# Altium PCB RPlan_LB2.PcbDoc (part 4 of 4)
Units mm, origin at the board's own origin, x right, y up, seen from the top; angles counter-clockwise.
Board outline 38.2 x 43.28 mm, 2 copper layers (Top Layer, Bottom Layer); 36 components, 100 nets, 269 pads, 31 vias.
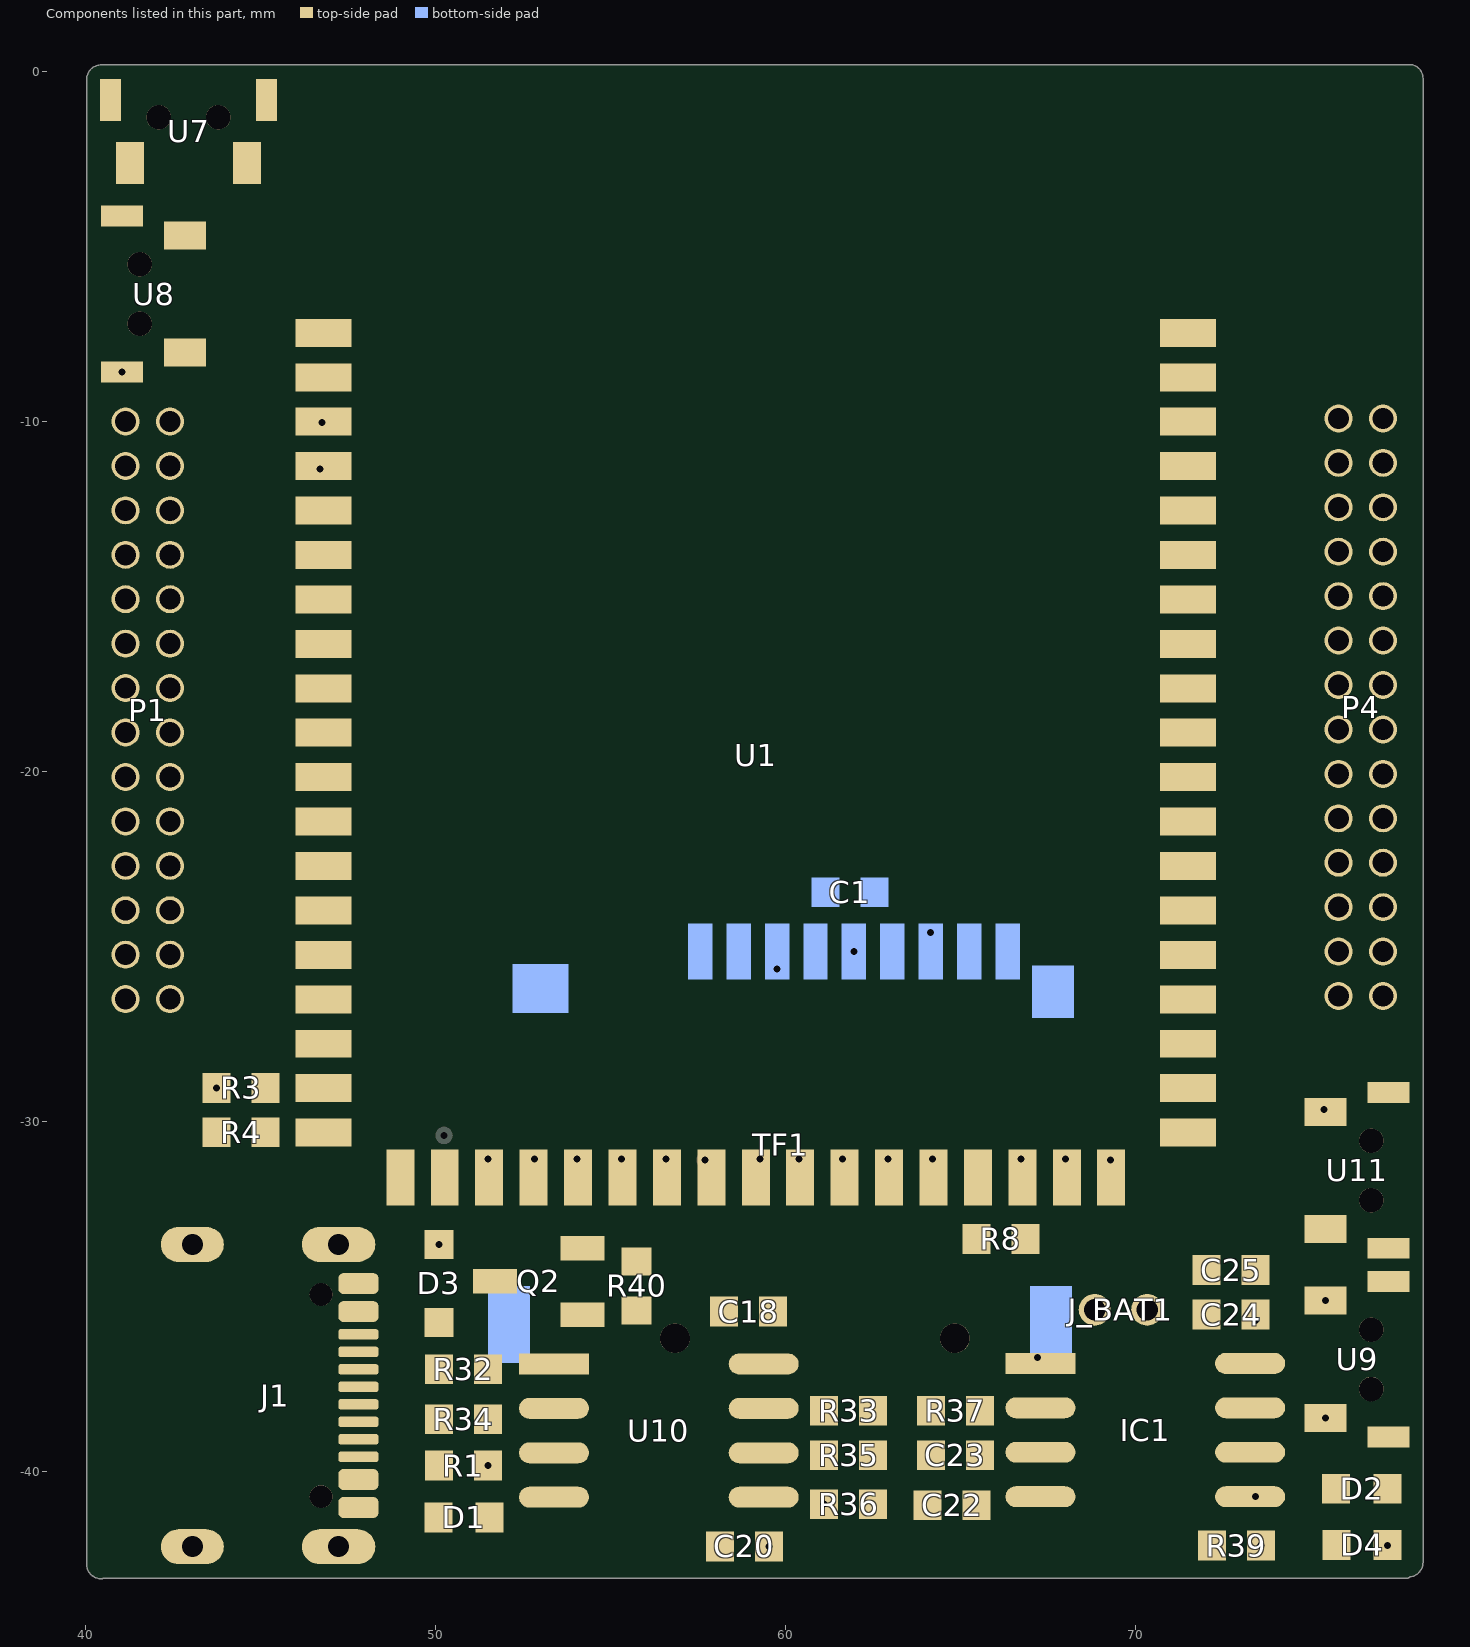
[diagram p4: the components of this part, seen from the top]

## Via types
v1: diameter 0.5, hole 0.3, Top Layer to Bottom Layer, 28 vias
v2: diameter 0.4, hole 0.2, Top Layer to Bottom Layer, 3 vias

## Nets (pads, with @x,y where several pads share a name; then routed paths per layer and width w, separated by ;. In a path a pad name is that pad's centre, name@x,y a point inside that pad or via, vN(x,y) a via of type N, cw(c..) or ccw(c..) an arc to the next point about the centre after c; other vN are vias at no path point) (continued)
copper on no net: (continued)
  Bottom Layer w0.025: 60.612,-15.207 60.84,-15.207 ; 60.612,-15.182 60.84,-15.182 ; 60.612,-15.156 60.84,-15.156 ; 60.612,-15.131 60.84,-15.131 ; 60.612,-15.105 61.196,-15.105 ; 60.815,-21.049 61.196,-21.049 ; 60.815,-21.024 61.145,-21.024 ; 60.815,-20.998 61.145,-20.998 ; 60.815,-20.973 61.145,-20.973 ; 60.815,-20.947 61.145,-20.947 ; 60.815,-20.922 61.145,-20.922 ; 60.815,-20.897 61.145,-20.897 ; 60.815,-20.871 61.145,-20.871 ; 60.815,-20.846 61.145,-20.846 ; 60.815,-20.82 61.196,-20.82 ; 60.815,-20.795 61.196,-20.795 ; 60.815,-20.77 61.196,-20.77 ; 60.815,-19.068 61.196,-19.068 ; 60.815,-19.042 61.145,-19.042 ; 60.815,-19.017 61.145,-19.017 ; 60.815,-18.992 61.145,-18.992 ; 60.815,-18.966 61.196,-18.966 ; 60.815,-18.941 61.196,-18.941 ; 60.815,-18.915 61.196,-18.915 ; 60.815,-18.89 61.196,-18.89 ; 60.815,-18.865 61.196,-18.865 ; 60.815,-18.839 61.196,-18.839 ; 60.815,-18.814 61.196,-18.814 ; 60.815,-18.788 61.196,-18.788 ; 60.815,-18.382 62.186,-18.382 ; 60.815,-18.357 62.186,-18.357 ; 60.815,-18.331 62.186,-18.331 ; 60.815,-18.306 62.186,-18.306 ; 60.815,-18.28 62.186,-18.28 ; 60.815,-18.255 62.186,-18.255 ; 60.815,-18.23 62.186,-18.23 ; 60.815,-18.204 62.186,-18.204 ; 60.815,-18.179 62.186,-18.179 ; 60.815,-18.153 62.186,-18.153 ; 60.815,-18.128 62.948,-18.128 ; 60.815,-18.103 62.948,-18.103 ; 60.815,-15.766 61.145,-15.766 ; 60.815,-15.74 61.145,-15.74 ; 60.815,-15.715 61.145,-15.715 ; 60.815,-15.69 61.145,-15.69 ; 60.815,-15.664 61.145,-15.664 ; 60.815,-15.639 61.145,-15.639 ; 60.815,-15.613 61.145,-15.613 ; 60.815,-15.588 61.145,-15.588 ; 60.815,-15.563 61.145,-15.563 ; 60.815,-15.537 61.145,-15.537 ; 60.815,-15.512 61.145,-15.512 ; 60.815,-15.486 61.196,-15.486 ; 60.815,-15.08 61.196,-15.08 ; 60.815,-15.055 61.196,-15.055 ; 60.815,-15.029 61.145,-15.029 ; 60.815,-15.004 61.145,-15.004 ; 60.815,-14.978 61.145,-14.978 ; 60.815,-14.953 61.196,-14.953 ; 60.815,-14.928 61.196,-14.928 ; 60.815,-14.902 61.196,-14.902 ; 60.815,-14.877 61.196,-14.877 ; 60.815,-14.851 61.196,-14.851 ; 60.815,-14.826 61.196,-14.826 ; 60.815,-14.801 61.196,-14.801 ; 60.815,-14.775 61.831,-14.775 ; 60.815,-14.75 61.831,-14.75 ; 60.815,-14.724 61.831,-14.724 ; 60.815,-14.699 61.831,-14.699 ; 60.815,-14.674 61.831,-14.674 ; 60.815,-14.648 61.831,-14.648 ; 60.815,-14.623 61.831,-14.623 ; 60.815,-14.597 61.831,-14.597 ; 60.815,-14.572 61.831,-14.572 ; 60.815,-14.547 61.831,-14.547 ; 60.815,-14.521 61.831,-14.521 ; 60.815,-14.496 61.831,-14.496 ; 60.815,-14.47 61.831,-14.47 ; 60.815,-14.445 61.831,-14.445 ; 60.815,-12.413 61.145,-12.413 ; 60.815,-12.388 61.145,-12.388 ; 60.815,-12.362 61.145,-12.362 ; 60.815,-12.337 61.145,-12.337 ; 60.815,-12.311 61.145,-12.311 ; 60.815,-12.286 61.196,-12.286 ; 60.815,-12.261 61.196,-12.261 ; 60.815,-12.235 61.196,-12.235 ; 60.815,-12.21 61.145,-12.21 ; 60.815,-12.184 61.145,-12.184 ; 60.815,-12.159 61.145,-12.159 ; 60.815,-12.134 61.145,-12.134 ; 60.815,-12.108 61.145,-12.108 ; 60.815,-12.083 61.145,-12.083 ; 60.815,-12.057 61.145,-12.057 ; 60.815,-12.032 61.145,-12.032 ; 60.815,-12.007 61.145,-12.007 ; 60.815,-11.981 61.196,-11.981 ; 60.815,-11.956 61.196,-11.956 ; 60.815,-11.93 61.196,-11.93 ; 60.815,-11.905 61.145,-11.905 ; 60.815,-11.88 61.145,-11.88 ; 60.815,-11.854 61.145,-11.854 ; 60.815,-11.829 61.196,-11.829 ; 60.815,-10.076 61.196,-10.076 ; 60.815,-10.051 61.196,-10.051 ; 60.815,-10.025 61.196,-10.025 ; 60.815,-10 61.145,-10 ; 60.815,-9.975 61.145,-9.975 ; 60.815,-9.949 61.145,-9.949 ; 60.815,-9.924 61.145,-9.924 ; 60.815,-9.898 61.145,-9.898 ; 60.815,-9.873 61.145,-9.873 ; 60.815,-9.848 61.145,-9.848 ; 60.815,-9.822 61.196,-9.822 ; 60.815,-9.797 61.196,-9.797 ; 61.145,-22.09 62.186,-22.09 ; 61.145,-22.065 62.186,-22.065 ; 61.145,-22.04 62.186,-22.04 ; 61.145,-22.014 62.186,-22.014 ; 61.145,-21.989 62.186,-21.989 ; 61.145,-21.963 62.186,-21.963 ; 61.145,-21.938 62.186,-21.938 ; 61.145,-21.913 62.186,-21.913 ; 61.145,-21.887 62.186,-21.887 ; 61.145,-21.862 62.186,-21.862 ; 61.145,-21.836 62.186,-21.836 ; 61.145,-21.811 62.186,-21.811 ; 61.145,-21.786 62.186,-21.786 ; 61.145,-21.76 62.186,-21.76 ; 61.145,-21.735 62.186,-21.735 ; 61.145,-21.709 62.186,-21.709 ; 61.145,-21.684 62.186,-21.684 ; 61.145,-21.659 62.186,-21.659 ; 61.145,-21.633 62.186,-21.633 ; 61.145,-21.608 62.186,-21.608 ; 61.145,-21.582 62.186,-21.582 ; 61.145,-21.557 62.186,-21.557 ; 61.145,-21.532 62.186,-21.532 ; 61.145,-21.506 62.186,-21.506 ; 61.145,-21.481 62.186,-21.481 ; 61.145,-21.455 62.186,-21.455 ; 61.145,-21.43 62.491,-21.43 ; 61.145,-18.077 61.526,-18.077 ; 61.145,-18.052 61.501,-18.052 ; 61.145,-18.026 61.501,-18.026 ; 61.145,-18.001 61.501,-18.001 ; 61.145,-17.976 61.501,-17.976 ; 61.145,-17.95 61.501,-17.95 ; 61.145,-17.925 61.501,-17.925 ; 61.145,-17.899 61.501,-17.899 ; 61.145,-17.874 61.501,-17.874 ; 61.145,-17.849 61.501,-17.849 ; 61.145,-17.823 61.501,-17.823 ; 61.145,-17.798 61.501,-17.798 ; 61.145,-17.391 61.831,-17.391 ; 61.145,-17.366 61.831,-17.366 ; 61.145,-17.341 61.831,-17.341 ; 61.145,-17.315 61.831,-17.315 ; 61.145,-17.29 61.831,-17.29 ; 61.145,-17.264 61.831,-17.264 ; 61.145,-17.239 61.831,-17.239 ; 61.145,-17.214 61.831,-17.214 ; 61.145,-17.188 61.831,-17.188 ; 61.145,-17.163 61.831,-17.163 ; 61.145,-17.137 61.831,-17.137 ; 61.145,-17.112 61.831,-17.112 ; 61.145,-16.401 62.821,-16.401 ; 61.145,-16.375 62.821,-16.375 ; 61.145,-16.35 62.821,-16.35 ; 61.145,-16.325 62.821,-16.325 ; 61.145,-16.299 62.821,-16.299 ; 61.145,-16.274 62.821,-16.274 ; 61.145,-16.248 62.821,-16.248 ; 61.145,-16.223 62.821,-16.223 ; 61.145,-16.198 62.821,-16.198 ; 61.145,-16.172 62.821,-16.172 ; 61.145,-16.147 62.821,-16.147 ; 61.145,-16.121 62.821,-16.121 ; 61.145,-14.42 61.501,-14.42 ; 61.145,-14.394 61.501,-14.394 ; 61.145,-14.369 61.501,-14.369 ; 61.145,-14.343 61.501,-14.343 ; 61.145,-14.318 61.501,-14.318 ; 61.145,-14.293 61.501,-14.293 ; 61.145,-14.267 61.501,-14.267 ; 61.145,-14.242 61.501,-14.242 ; 61.145,-14.216 61.501,-14.216 ; 61.145,-14.191 61.501,-14.191 ; 61.145,-14.166 61.501,-14.166 ; 61.145,-14.14 61.501,-14.14 ; 61.145,-13.734 61.501,-13.734 ; 61.145,-13.708 61.501,-13.708 ; 61.145,-13.683 61.501,-13.683 ; 61.145,-13.658 61.501,-13.658 ; 61.145,-13.632 61.501,-13.632 ; 61.145,-13.607 61.501,-13.607 ; 61.145,-13.581 61.501,-13.581 ; 61.145,-13.556 61.501,-13.556 ; 61.145,-13.531 61.501,-13.531 ; 61.145,-13.505 61.501,-13.505 ; 61.145,-10.432 62.186,-10.432 ; 61.145,-10.406 62.186,-10.406 ; 61.145,-10.381 62.186,-10.381 ; 61.145,-10.356 62.186,-10.356 ; 61.145,-10.33 62.186,-10.33 ; 61.145,-10.305 62.186,-10.305 ; 61.145,-10.279 62.186,-10.279 ; 61.145,-10.254 62.186,-10.254 ; 61.145,-10.229 62.186,-10.229 ; 61.145,-10.203 62.186,-10.203 ; 61.145,-10.178 62.186,-10.178 ; 61.145,-10.152 62.186,-10.152 ; 61.45,-20.744 62.517,-20.744 ; 61.45,-20.719 62.517,-20.719 ; 61.45,-20.693 62.517,-20.693 ; 61.45,-20.668 62.517,-20.668 ; 61.45,-20.643 62.517,-20.643 ; 61.45,-20.617 62.517,-20.617 ; 61.45,-20.592 62.517,-20.592 ; 61.45,-20.566 62.517,-20.566 ; 61.45,-20.541 62.517,-20.541 ; 61.45,-20.516 62.517,-20.516 ; 61.45,-20.49 62.517,-20.49 ; 61.45,-20.465 62.517,-20.465 ; 61.45,-19.068 61.831,-19.068 ; 61.45,-19.042 61.831,-19.042 ; 61.45,-19.017 61.831,-19.017 ; 61.45,-18.992 61.831,-18.992 ; 61.45,-18.966 61.831,-18.966 ; 61.45,-18.941 61.831,-18.941 ; 61.45,-18.915 61.831,-18.915 ; 61.45,-18.89 61.831,-18.89 ; 61.45,-18.865 61.831,-18.865 ; 61.45,-18.839 61.831,-18.839 ; 61.45,-18.814 61.831,-18.814 ; 61.45,-18.788 61.831,-18.788 ; 61.45,-16.096 63.177,-16.096 ; 61.45,-16.071 63.177,-16.071 ; 61.45,-16.045 63.177,-16.045 ; 61.45,-16.02 63.177,-16.02 ; 61.45,-15.994 63.177,-15.994 ; 61.45,-15.969 63.177,-15.969 ; 61.45,-15.944 63.177,-15.944 ; 61.45,-15.918 63.177,-15.918 ; 61.45,-15.893 63.177,-15.893 ; 61.45,-15.867 63.177,-15.867 ; 61.45,-15.842 63.177,-15.842 ; 61.45,-15.817 63.177,-15.817 ; 61.45,-15.791 63.177,-15.791 ; 61.45,-15.766 61.831,-15.766 ; 61.45,-15.74 61.831,-15.74 ; 61.45,-15.715 61.831,-15.715 ; 61.45,-15.69 61.831,-15.69 ; 61.45,-15.664 61.831,-15.664 ; 61.45,-15.639 61.831,-15.639 ; 61.45,-15.613 61.831,-15.613 ; 61.45,-15.588 61.831,-15.588 ; 61.45,-15.563 61.831,-15.563 ; 61.45,-15.537 61.831,-15.537 ; 61.45,-15.512 61.831,-15.512 ; 61.45,-15.486 61.831,-15.486 ; 61.45,-15.461 64.853,-15.461 ; 61.45,-15.436 64.853,-15.436 ; 61.45,-15.105 63.177,-15.105 ; 61.45,-15.08 62.186,-15.08 ; 61.45,-15.055 62.186,-15.055 ; 61.45,-15.029 62.186,-15.029 ; 61.45,-15.004 62.186,-15.004 ; 61.45,-14.978 62.186,-14.978 ; 61.45,-14.953 62.186,-14.953 ; 61.45,-14.928 62.186,-14.928 ; 61.45,-14.902 62.186,-14.902 ; 61.45,-14.877 62.186,-14.877 ; 61.45,-14.851 62.186,-14.851 ; 61.45,-14.826 62.186,-14.826 ; 61.45,-14.801 62.186,-14.801 ; 61.45,-14.089 61.831,-14.089 ; 61.45,-14.064 61.831,-14.064 ; 61.45,-14.039 61.831,-14.039 ; 61.45,-14.013 61.831,-14.013 ; 61.45,-13.988 61.831,-13.988 ; 61.45,-13.962 61.831,-13.962 ; 61.45,-13.937 61.831,-13.937 ; 61.45,-13.912 61.831,-13.912 ; 61.45,-13.886 61.831,-13.886 ; 61.45,-13.861 61.831,-13.861 ; 61.45,-13.835 61.831,-13.835 ; 61.45,-13.81 61.831,-13.81 ; 61.45,-13.429 61.831,-13.429 ; 61.45,-13.404 61.831,-13.404 ; 61.45,-13.378 61.831,-13.378 ; 61.45,-13.353 61.831,-13.353 ; 61.45,-13.327 61.831,-13.327 ; 61.45,-13.302 61.831,-13.302 ; 61.45,-13.277 61.831,-13.277 ; 61.45,-13.251 61.831,-13.251 ; 61.45,-13.226 61.831,-13.226 ; 61.45,-13.2 61.831,-13.2 ; 61.45,-13.175 61.831,-13.175 ; 61.45,-13.15 61.831,-13.15 ; 61.45,-13.124 61.831,-13.124 ; 61.45,-13.099 61.831,-13.099 ; 61.45,-13.073 61.831,-13.073 ; 61.45,-13.048 61.831,-13.048 ; 61.45,-13.023 61.831,-13.023 ; 61.45,-12.997 61.831,-12.997 ; 61.45,-12.972 61.831,-12.972 ; 61.45,-12.946 61.831,-12.946 ; 61.45,-12.921 61.831,-12.921 ; 61.45,-12.896 61.831,-12.896 ; 61.45,-12.87 61.831,-12.87 ; 61.45,-12.845 61.831,-12.845 ; 61.45,-12.819 61.831,-12.819 ; 61.45,-12.108 61.831,-12.108 ; 61.45,-12.083 61.831,-12.083 ; 61.45,-12.057 61.831,-12.057 ; 61.45,-12.032 61.831,-12.032 ; 61.45,-12.007 61.831,-12.007 ; 61.45,-11.981 61.831,-11.981 ; 61.45,-11.956 61.831,-11.956 ; 61.45,-11.93 61.831,-11.93 ; 61.45,-11.905 61.831,-11.905 ; 61.45,-11.88 61.831,-11.88 ; 61.45,-11.854 61.831,-11.854 ; 61.45,-11.829 61.831,-11.829 ; 61.45,-11.803 62.517,-11.803 ; 61.45,-11.778 62.517,-11.778 ; 61.45,-10.076 62.517,-10.076 ; 61.45,-10.051 62.517,-10.051 ; 61.45,-10.025 62.517,-10.025 ; 61.45,-10 62.517,-10 ; 61.45,-9.975 62.517,-9.975 ; 61.45,-9.949 62.517,-9.949 ; 61.45,-9.924 62.517,-9.924 ; 61.45,-9.898 62.517,-9.898 ; 61.45,-9.873 62.517,-9.873 ; 61.45,-9.848 62.517,-9.848 ; 61.45,-9.822 62.517,-9.822 ; 61.45,-9.797 62.517,-9.797 ; 61.501,-12.134 61.831,-12.134 ; 61.805,-17.087 62.821,-17.087 ; 61.805,-17.061 62.821,-17.061 ; 61.805,-17.036 62.821,-17.036 ; 61.805,-17.01 62.821,-17.01 ; 61.805,-16.985 62.821,-16.985 ; 61.805,-16.96 62.821,-16.96 ; 61.805,-16.934 62.821,-16.934 ; 61.805,-16.909 62.821,-16.909 ; 61.805,-16.883 62.821,-16.883 ; 61.805,-16.858 62.821,-16.858 ; 61.805,-16.833 62.821,-16.833 ; 61.805,-16.807 62.821,-16.807 ; 61.805,-16.782 65.158,-16.782 ; 61.805,-15.41 63.177,-15.41 ; 61.805,-15.385 63.177,-15.385 ; 61.805,-15.359 63.177,-15.359 ; 61.805,-15.334 63.177,-15.334 ; 61.805,-15.309 63.177,-15.309 ; 61.805,-15.283 63.177,-15.283 ; 61.805,-15.258 63.177,-15.258 ; 61.805,-15.232 63.177,-15.232 ; 61.805,-15.207 63.177,-15.207 ; 61.805,-15.182 63.177,-15.182 ; 61.805,-15.156 63.177,-15.156 ; 61.805,-15.131 63.177,-15.131 ; 61.805,-13.734 62.186,-13.734 ; 61.805,-13.708 62.186,-13.708 ; 61.805,-13.683 62.186,-13.683 ; 61.805,-13.658 62.186,-13.658 ; 61.805,-13.632 62.186,-13.632 ; 61.805,-13.607 62.186,-13.607 ; 61.805,-13.581 62.186,-13.581 ; 61.805,-13.556 62.186,-13.556 ; 61.805,-13.531 62.186,-13.531 ; 61.805,-13.505 62.186,-13.505 ; 61.805,-11.753 62.186,-11.753 ; 61.805,-11.727 62.186,-11.727 ; 61.805,-11.702 62.186,-11.702 ; 61.805,-11.676 62.186,-11.676 ; 61.805,-11.651 62.186,-11.651 ; 61.805,-11.626 62.186,-11.626 ; 61.805,-11.6 62.186,-11.6 ; 61.805,-11.575 62.186,-11.575 ; 61.805,-11.549 62.186,-11.549 ; 61.805,-11.524 62.186,-11.524 ; 61.805,-11.499 62.186,-11.499 ; 61.805,-11.473 62.186,-11.473 ; 61.805,-11.448 62.186,-11.448 ; 61.805,-11.422 62.186,-11.422 ; 61.805,-11.397 62.186,-11.397 ; 61.805,-11.372 62.186,-11.372 ; 61.805,-11.346 62.186,-11.346 ; 61.805,-11.321 62.186,-11.321 ; 61.805,-11.295 62.186,-11.295 ; 61.805,-11.27 62.186,-11.27 ; 61.805,-11.245 62.186,-11.245 ; 61.805,-11.219 62.186,-11.219 ; 61.805,-11.194 62.186,-11.194 ; 61.805,-11.168 62.186,-11.168 ; 61.805,-11.143 62.186,-11.143 ; 62.136,-21.405 62.517,-21.405 ; 62.136,-21.379 62.517,-21.379 ; 62.136,-21.354 62.517,-21.354 ; 62.136,-21.328 62.517,-21.328 ; 62.136,-21.303 62.517,-21.303 ; 62.136,-21.278 62.517,-21.278 ; 62.136,-21.252 62.517,-21.252 ; 62.136,-21.227 62.517,-21.227 ; 62.136,-21.201 62.517,-21.201 ; 62.136,-21.176 62.517,-21.176 ; 62.136,-21.151 62.517,-21.151 ; 62.136,-21.125 62.517,-21.125 ; 62.136,-21.1 62.491,-21.1 ; 62.136,-21.074 62.491,-21.074 ; 62.136,-20.414 62.517,-20.414 ; 62.136,-20.389 62.517,-20.389 ; 62.136,-20.363 62.517,-20.363 ; 62.136,-20.338 62.517,-20.338 ; 62.136,-20.312 62.517,-20.312 ; 62.136,-20.287 62.517,-20.287 ; 62.136,-20.262 62.517,-20.262 ; 62.136,-20.236 62.517,-20.236 ; 62.136,-20.211 62.517,-20.211 ; 62.136,-20.185 62.517,-20.185 ; 62.136,-20.16 62.517,-20.16 ; 62.136,-20.135 62.517,-20.135 ; 62.136,-20.109 62.491,-20.109 ; 62.136,-20.084 62.491,-20.084 ; 62.136,-19.754 62.517,-19.754 ; 62.136,-19.728 62.517,-19.728 ; 62.136,-19.703 62.517,-19.703 ; 62.136,-19.677 62.517,-19.677 ; 62.136,-19.652 62.517,-19.652 ; 62.136,-19.627 62.517,-19.627 ; 62.136,-19.601 62.517,-19.601 ; 62.136,-19.576 62.517,-19.576 ; 62.136,-19.55 62.517,-19.55 ; 62.136,-19.525 62.517,-19.525 ; 62.136,-19.5 62.517,-19.5 ; 62.136,-19.474 62.517,-19.474 ; 62.136,-19.068 62.821,-19.068 ; 62.136,-19.042 62.821,-19.042 ; 62.136,-19.017 62.821,-19.017 ; 62.136,-18.992 62.821,-18.992 ; 62.136,-18.966 62.821,-18.966 ; 62.136,-18.941 62.821,-18.941 ; 62.136,-18.915 62.821,-18.915 ; 62.136,-18.89 62.821,-18.89 ; 62.136,-18.865 62.821,-18.865 ; 62.136,-18.839 62.821,-18.839 ; 62.136,-18.814 62.821,-18.814 ; 62.136,-18.788 62.821,-18.788 ; 62.136,-18.763 65.158,-18.763 ; 62.136,-18.077 63.177,-18.077 ; 62.136,-18.052 63.177,-18.052 ; 62.136,-18.026 63.177,-18.026 ; 62.136,-18.001 63.177,-18.001 ; 62.136,-17.976 63.177,-17.976 ; 62.136,-17.95 63.177,-17.95 ; 62.136,-17.925 63.177,-17.925 ; 62.136,-17.899 63.177,-17.899 ; 62.136,-17.874 63.177,-17.874 ; 62.136,-17.849 63.177,-17.849 ; 62.136,-17.823 63.177,-17.823 ; 62.136,-17.798 63.177,-17.798 ; 62.136,-17.772 63.177,-17.772 ; 62.136,-16.756 62.517,-16.756 ; 62.136,-16.731 62.517,-16.731 ; 62.136,-16.706 62.517,-16.706 ; 62.136,-16.68 62.517,-16.68 ; 62.136,-16.655 62.517,-16.655 ; 62.136,-16.629 62.517,-16.629 ; 62.136,-16.604 62.517,-16.604 ; 62.136,-16.579 62.517,-16.579 ; 62.136,-16.553 62.517,-16.553 ; 62.136,-16.528 62.517,-16.528 ; 62.136,-16.502 62.517,-16.502 ; 62.136,-16.477 62.517,-16.477 ; 62.136,-14.115 63.507,-14.115 ; 62.136,-14.089 63.177,-14.089 ; 62.136,-14.064 63.177,-14.064 ; 62.136,-14.039 63.177,-14.039 ; 62.136,-14.013 63.177,-14.013 ; 62.136,-13.988 63.177,-13.988 ; 62.136,-13.962 63.177,-13.962 ; 62.136,-13.937 63.177,-13.937 ; 62.136,-13.912 63.177,-13.912 ; 62.136,-13.886 63.177,-13.886 ; 62.136,-13.861 63.177,-13.861 ; 62.136,-13.835 63.177,-13.835 ; 62.136,-13.81 63.177,-13.81 ; 62.136,-13.429 63.177,-13.429 ; 62.136,-13.404 63.177,-13.404 ; 62.136,-13.378 63.177,-13.378 ; 62.136,-13.353 63.177,-13.353 ; 62.136,-13.327 63.177,-13.327 ; 62.136,-13.302 63.177,-13.302 ; 62.136,-13.277 63.177,-13.277 ; 62.136,-13.251 63.177,-13.251 ; 62.136,-13.226 63.177,-13.226 ; 62.136,-13.2 63.177,-13.2 ; 62.136,-13.175 63.177,-13.175 ; 62.136,-13.15 63.177,-13.15 ; 62.136,-13.124 63.177,-13.124 ; 62.136,-12.794 62.517,-12.794 ; 62.136,-12.769 62.517,-12.769 ; 62.136,-12.743 62.517,-12.743 ; 62.136,-12.718 62.517,-12.718 ; 62.136,-12.692 62.517,-12.692 ; 62.136,-12.667 62.517,-12.667 ; 62.136,-12.642 62.517,-12.642 ; 62.136,-12.616 62.517,-12.616 ; 62.136,-12.591 62.517,-12.591 ; 62.136,-12.565 62.517,-12.565 ; 62.136,-12.54 62.517,-12.54 ; 62.136,-12.515 62.517,-12.515 ; 62.136,-12.489 62.517,-12.489 ; 62.136,-12.464 62.517,-12.464 ; 62.136,-12.438 62.491,-12.438 ; 62.136,-12.134 62.491,-12.134 ; 62.136,-12.108 62.517,-12.108 ; 62.136,-12.083 62.517,-12.083 ; 62.136,-12.057 62.517,-12.057 ; 62.136,-12.032 62.517,-12.032 ; 62.136,-12.007 62.517,-12.007 ; 62.136,-11.981 62.517,-11.981 ; 62.136,-11.956 62.517,-11.956 ; 62.136,-11.93 62.517,-11.93 ; 62.136,-11.905 62.517,-11.905 ; 62.136,-11.88 62.517,-11.88 ; 62.136,-11.854 62.517,-11.854 ; 62.136,-11.829 62.517,-11.829 ; 62.136,-11.118 62.517,-11.118 ; 62.136,-11.092 62.517,-11.092 ; 62.136,-11.067 62.517,-11.067 ; 62.136,-11.041 62.517,-11.041 ; 62.136,-11.016 62.517,-11.016 ; 62.136,-10.991 62.517,-10.991 ; 62.136,-10.965 62.517,-10.965 ; 62.136,-10.94 62.517,-10.94 ; 62.136,-10.914 62.517,-10.914 ; 62.136,-10.889 62.517,-10.889 ; 62.136,-10.864 62.517,-10.864 ; 62.136,-10.838 62.517,-10.838 ; 62.136,-10.813 62.517,-10.813 ; 62.136,-10.787 62.517,-10.787 ; 62.491,-19.423 64.498,-19.423 ; 62.491,-19.398 64.498,-19.398 ; 62.491,-19.373 64.498,-19.373 ; 62.491,-19.347 64.498,-19.347 ; 62.491,-19.322 64.498,-19.322 ; 62.491,-19.296 64.498,-19.296 ; 62.491,-19.271 64.498,-19.271 ; 62.491,-19.246 64.498,-19.246 ; 62.491,-19.22 64.498,-19.22 ; 62.491,-19.195 64.498,-19.195 ; 62.491,-19.169 64.498,-19.169 ; 62.491,-19.144 64.498,-19.144 ; 62.491,-14.775 63.507,-14.775 ; 62.491,-14.75 63.507,-14.75 ; 62.491,-14.724 63.507,-14.724 ; 62.491,-14.699 63.507,-14.699 ; 62.491,-14.674 63.507,-14.674 ; 62.491,-14.648 63.507,-14.648 ; 62.491,-14.623 63.507,-14.623 ; 62.491,-14.597 63.507,-14.597 ; 62.491,-14.572 63.507,-14.572 ; 62.491,-14.547 63.507,-14.547 ; 62.491,-14.521 63.507,-14.521 ; 62.491,-14.496 63.507,-14.496 ; 62.491,-14.47 63.507,-14.47 ; 62.491,-14.445 63.507,-14.445 ; 62.491,-14.42 62.821,-14.42 ; 62.491,-14.394 62.821,-14.394 ; 62.491,-14.369 62.821,-14.369 ; 62.491,-14.343 62.821,-14.343 ; 62.491,-14.318 62.821,-14.318 ; 62.491,-14.293 62.821,-14.293 ; 62.491,-14.267 62.821,-14.267 ; 62.491,-14.242 62.821,-14.242 ; 62.491,-14.216 62.821,-14.216 ; 62.491,-14.191 62.821,-14.191 ; 62.491,-14.166 62.821,-14.166 ; 62.491,-14.14 62.821,-14.14 ; 62.491,-13.734 62.821,-13.734 ; 62.491,-13.708 62.821,-13.708 ; 62.491,-13.683 62.821,-13.683 ; 62.491,-13.658 62.821,-13.658 ; 62.491,-13.632 62.821,-13.632 ; 62.491,-13.607 62.821,-13.607 ; 62.491,-13.581 62.821,-13.581 ; 62.491,-13.556 62.821,-13.556 ; 62.491,-13.531 62.821,-13.531 ; 62.491,-13.505 62.821,-13.505 ; 62.796,-22.09 65.158,-22.09 ; 62.796,-22.065 65.158,-22.065 ; 62.796,-22.04 65.158,-22.04 ; 62.796,-22.014 65.158,-22.014 ; 62.796,-21.989 65.158,-21.989 ; 62.796,-21.963 65.158,-21.963 ; 62.796,-21.938 65.158,-21.938 ; 62.796,-21.913 65.158,-21.913 ; 62.796,-21.887 65.158,-21.887 ; 62.796,-21.862 65.158,-21.862 ; 62.796,-21.836 65.158,-21.836 ; 62.796,-21.811 65.158,-21.811 ; 62.796,-21.786 65.158,-21.786 ; 62.796,-21.76 65.158,-21.76 ; 62.796,-21.735 63.177,-21.735 ; 62.796,-21.709 63.177,-21.709 ; 62.796,-21.684 63.177,-21.684 ; 62.796,-21.659 63.177,-21.659 ; 62.796,-21.633 63.177,-21.633 ; 62.796,-21.608 63.177,-21.608 ; 62.796,-21.582 63.177,-21.582 ; 62.796,-21.557 63.177,-21.557 ; 62.796,-21.532 63.177,-21.532 ; 62.796,-21.506 63.177,-21.506 ; 62.796,-21.481 63.177,-21.481 ; 62.796,-21.455 63.177,-21.455 ; 62.796,-21.43 63.177,-21.43 ; 62.796,-21.405 63.177,-21.405 ; 62.796,-21.379 63.177,-21.379 ; 62.796,-21.354 63.177,-21.354 ; 62.796,-21.328 63.177,-21.328 ; 62.796,-21.303 63.177,-21.303 ; 62.796,-21.278 63.177,-21.278 ; 62.796,-21.252 63.177,-21.252 ; 62.796,-21.227 63.177,-21.227 ; 62.796,-21.201 63.177,-21.201 ; 62.796,-21.176 63.177,-21.176 ; 62.796,-21.151 63.177,-21.151 ; 62.796,-21.125 63.177,-21.125 ; 62.796,-21.1 63.177,-21.1 ; 62.796,-21.074 63.177,-21.074 ; 62.796,-21.049 63.177,-21.049 ; 62.796,-21.024 63.177,-21.024 ; 62.796,-20.998 63.177,-20.998 ; 62.796,-20.973 63.177,-20.973 ; 62.796,-20.947 63.177,-20.947 ; 62.796,-20.922 63.177,-20.922 ; 62.796,-20.897 63.177,-20.897 ; 62.796,-20.871 63.177,-20.871 ; 62.796,-20.846 63.177,-20.846 ; 62.796,-20.82 63.177,-20.82 ; 62.796,-20.795 63.177,-20.795 ; 62.796,-20.77 63.177,-20.77 ; 62.796,-20.744 63.177,-20.744 ; 62.796,-20.719 63.177,-20.719 ; 62.796,-20.693 63.177,-20.693 ; 62.796,-20.668 63.177,-20.668 ; 62.796,-20.643 63.177,-20.643 ; 62.796,-20.617 63.177,-20.617 ; 62.796,-20.592 63.177,-20.592 ; 62.796,-20.566 63.177,-20.566 ; 62.796,-20.541 63.177,-20.541 ; 62.796,-20.516 63.177,-20.516 ; 62.796,-20.49 63.177,-20.49 ; 62.796,-20.465 63.177,-20.465 ; 62.796,-20.439 63.177,-20.439 ; 62.796,-20.414 63.177,-20.414 ; 62.796,-20.389 63.177,-20.389 ; 62.796,-20.363 63.177,-20.363 ; 62.796,-20.338 63.177,-20.338 ; 62.796,-20.312 63.177,-20.312 ; 62.796,-20.287 63.177,-20.287 ; 62.796,-20.262 63.177,-20.262 ; 62.796,-20.236 63.177,-20.236 ; 62.796,-20.211 63.177,-20.211 ; 62.796,-20.185 63.177,-20.185 ; 62.796,-20.16 63.177,-20.16 ; 62.796,-20.135 63.177,-20.135 ; 62.796,-20.109 65.158,-20.109 ; 62.796,-20.084 65.158,-20.084 ; 62.796,-20.058 65.158,-20.058 ; 62.796,-20.033 65.158,-20.033 ; 62.796,-20.008 65.158,-20.008 ; 62.796,-19.982 65.158,-19.982 ; 62.796,-19.957 65.158,-19.957 ; 62.796,-19.931 65.158,-19.931 ; 62.796,-19.906 65.158,-19.906 ; 62.796,-19.881 65.158,-19.881 ; 62.796,-19.855 65.158,-19.855 ; 62.796,-19.83 65.158,-19.83 ; 62.796,-19.804 65.158,-19.804 ; 62.796,-19.779 65.158,-19.779 ; 62.796,-18.738 64.498,-18.738 ; 62.796,-18.712 64.498,-18.712 ; 62.796,-18.687 64.498,-18.687 ; 62.796,-18.661 64.498,-18.661 ; 62.796,-18.636 64.498,-18.636 ; 62.796,-18.611 64.498,-18.611 ; 62.796,-18.585 64.498,-18.585 ; 62.796,-18.56 64.498,-18.56 ; 62.796,-18.534 64.498,-18.534 ; 62.796,-18.509 64.498,-18.509 ; 62.796,-18.484 64.498,-18.484 ; 62.796,-18.458 64.498,-18.458 ; 62.796,-17.442 65.158,-17.442 ; 62.796,-17.417 65.158,-17.417 ; 62.796,-17.391 64.168,-17.391 ; 62.796,-17.366 64.168,-17.366 ; 62.796,-17.341 64.168,-17.341 ; 62.796,-17.315 64.168,-17.315 ; 62.796,-17.29 64.168,-17.29 ; 62.796,-17.264 64.168,-17.264 ; 62.796,-17.239 64.168,-17.239 ; 62.796,-17.214 64.168,-17.214 ; 62.796,-17.188 64.168,-17.188 ; 62.796,-17.163 64.168,-17.163 ; 62.796,-17.137 64.168,-17.137 ; 62.796,-17.112 64.168,-17.112 ; 62.796,-16.756 64.498,-16.756 ; 62.796,-16.731 64.498,-16.731 ; 62.796,-16.706 64.498,-16.706 ; 62.796,-16.68 64.498,-16.68 ; 62.796,-16.655 64.498,-16.655 ; 62.796,-16.629 64.498,-16.629 ; 62.796,-16.604 64.498,-16.604 ; 62.796,-16.579 64.498,-16.579 ; 62.796,-16.553 64.498,-16.553 ; 62.796,-16.528 64.498,-16.528 ; 62.796,-16.502 64.498,-16.502 ; 62.796,-16.477 64.498,-16.477 ; 62.796,-12.794 64.803,-12.794 ; 62.796,-12.769 64.803,-12.769 ; 62.796,-12.743 63.812,-12.743 ; 62.796,-12.718 63.812,-12.718 ; 62.796,-12.692 63.812,-12.692 ; 62.796,-12.667 63.812,-12.667 ; 62.796,-12.642 63.812,-12.642 ; 62.796,-12.616 63.812,-12.616 ; 62.796,-12.591 63.812,-12.591 ; 62.796,-12.565 63.812,-12.565 ; 62.796,-12.54 63.812,-12.54 ; 62.796,-12.515 63.812,-12.515 ; 62.796,-12.489 63.812,-12.489 ; 62.796,-12.464 63.812,-12.464 ; 62.796,-12.108 65.158,-12.108 ; 62.796,-12.083 65.158,-12.083 ; 62.796,-12.057 65.158,-12.057 ; 62.796,-12.032 65.158,-12.032 ; 62.796,-12.007 65.158,-12.007 ; 62.796,-11.981 65.158,-11.981 ; 62.796,-11.956 65.158,-11.956 ; 62.796,-11.93 65.158,-11.93 ; 62.796,-11.905 65.158,-11.905 ; 62.796,-11.88 65.158,-11.88 ; 62.796,-11.854 65.158,-11.854 ; 62.796,-11.829 65.158,-11.829 ; 62.796,-11.803 65.158,-11.803 ; 62.796,-11.778 65.158,-11.778 ; 62.796,-11.753 63.177,-11.753 ; 62.796,-11.727 63.177,-11.727 ; 62.796,-11.702 63.177,-11.702 ; 62.796,-11.676 63.177,-11.676 ; 62.796,-11.651 63.177,-11.651 ; 62.796,-11.626 63.177,-11.626 ; 62.796,-11.6 63.177,-11.6 ; 62.796,-11.575 63.177,-11.575 ; 62.796,-11.549 63.177,-11.549 ; 62.796,-11.524 63.177,-11.524 ; 62.796,-11.499 63.177,-11.499 ; 62.796,-11.473 63.177,-11.473 ; 62.796,-11.448 63.177,-11.448 ; 62.796,-11.422 63.177,-11.422 ; 62.796,-11.397 63.177,-11.397 ; 62.796,-11.372 63.177,-11.372 ; 62.796,-11.346 63.177,-11.346 ; 62.796,-11.321 63.177,-11.321 ; 62.796,-11.295 63.177,-11.295 ; 62.796,-11.27 63.177,-11.27 ; 62.796,-11.245 63.177,-11.245 ; 62.796,-11.219 63.177,-11.219 ; 62.796,-11.194 63.177,-11.194 ; 62.796,-11.168 63.177,-11.168 ; 62.796,-11.143 63.177,-11.143 ; 62.796,-11.118 63.177,-11.118 ; 62.796,-11.092 63.177,-11.092 ; 62.796,-11.067 63.177,-11.067 ; 62.796,-11.041 63.177,-11.041 ; 62.796,-11.016 63.177,-11.016 ; 62.796,-10.991 63.177,-10.991 ; 62.796,-10.965 63.177,-10.965 ; 62.796,-10.94 63.177,-10.94 ; 62.796,-10.914 63.177,-10.914 ; 62.796,-10.889 63.177,-10.889 ; 62.796,-10.864 63.177,-10.864 ; 62.796,-10.838 63.177,-10.838 ; 62.796,-10.813 63.177,-10.813 ; 62.796,-10.787 63.177,-10.787 ; 62.796,-10.762 63.177,-10.762 ; 62.796,-10.737 63.177,-10.737 ; 62.796,-10.711 63.177,-10.711 ; 62.796,-10.686 63.177,-10.686 ; 62.796,-10.66 63.177,-10.66 ; 62.796,-10.635 63.177,-10.635 ; 62.796,-10.61 63.177,-10.61 ; 62.796,-10.584 63.177,-10.584 ; 62.796,-10.559 63.177,-10.559 ; 62.796,-10.533 63.177,-10.533 ; 62.796,-10.508 63.177,-10.508 ; 62.796,-10.483 63.177,-10.483 ; 62.796,-10.457 63.177,-10.457 ; 62.796,-10.432 63.177,-10.432 ; 62.796,-10.406 63.177,-10.406 ; 62.796,-10.381 63.177,-10.381 ; 62.796,-10.356 63.177,-10.356 ; 62.796,-10.33 63.177,-10.33 ; 62.796,-10.305 63.177,-10.305 ; 62.796,-10.279 63.177,-10.279 ; 62.796,-10.254 63.177,-10.254 ; 62.796,-10.229 63.177,-10.229 ; 62.796,-10.203 63.177,-10.203 ; 62.796,-10.178 63.177,-10.178 ; 62.796,-10.152 63.177,-10.152 ; 62.796,-10.127 65.158,-10.127 ; 62.796,-10.102 65.158,-10.102 ; 62.796,-10.076 65.158,-10.076 ; 62.796,-10.051 65.158,-10.051 ; 62.796,-10.025 65.158,-10.025 ; 62.796,-10 65.158,-10 ; 62.796,-9.975 65.158,-9.975 ; 62.796,-9.949 65.158,-9.949 ; 62.796,-9.924 65.158,-9.924 ; 62.796,-9.898 65.158,-9.898 ; 62.796,-9.873 65.158,-9.873 ; 62.796,-9.848 65.158,-9.848 ; 62.796,-9.822 65.158,-9.822 ; 62.796,-9.797 65.158,-9.797 ; 62.821,-19.754 65.158,-19.754 ; 62.821,-18.433 65.158,-18.433 ; 62.821,-18.407 65.158,-18.407 ; 62.821,-12.438 63.812,-12.438 ; 62.821,-12.134 65.158,-12.134 ; 62.974,-13.785 63.177,-13.785 ; 62.974,-13.759 63.177,-13.759 ; 63.101,-18.128 63.177,-18.128 ; 63.101,-18.103 63.177,-18.103 ; 63.126,-17.087 63.507,-17.087 ; 63.126,-17.061 63.507,-17.061 ; 63.126,-17.036 63.507,-17.036 ; 63.126,-17.01 63.507,-17.01 ; 63.126,-16.985 63.507,-16.985 ; 63.126,-16.96 63.507,-16.96 ; 63.126,-16.934 63.507,-16.934 ; 63.126,-16.909 63.507,-16.909 ; 63.126,-16.883 63.507,-16.883 ; 63.126,-16.858 63.507,-16.858 ; 63.126,-16.833 63.507,-16.833 ; 63.126,-16.807 63.507,-16.807 ; 63.126,-15.766 63.812,-15.766 ; 63.126,-15.74 63.812,-15.74 ; 63.126,-15.715 63.812,-15.715 ; 63.126,-15.69 63.812,-15.69 ; 63.126,-15.664 63.812,-15.664 ; 63.126,-15.639 63.812,-15.639 ; 63.126,-15.613 63.812,-15.613 ; 63.126,-15.588 63.812,-15.588 ; 63.126,-15.563 63.812,-15.563 ; 63.126,-15.537 63.812,-15.537 ; 63.126,-15.512 63.812,-15.512 ; 63.126,-15.486 63.812,-15.486 ; 63.126,-14.42 63.507,-14.42 ; 63.126,-14.394 63.507,-14.394 ; 63.126,-14.369 63.507,-14.369 ; 63.126,-14.343 63.507,-14.343 ; 63.126,-14.318 63.507,-14.318 ; 63.126,-14.293 63.507,-14.293 ; 63.126,-14.267 63.507,-14.267 ; 63.126,-14.242 63.507,-14.242 ; 63.126,-14.216 63.507,-14.216 ; 63.126,-14.191 63.507,-14.191 ; 63.126,-14.166 63.507,-14.166 ; 63.126,-14.14 63.507,-14.14 ; 63.482,-21.43 64.498,-21.43 ; 63.482,-21.405 64.498,-21.405 ; 63.482,-21.379 64.498,-21.379 ; 63.482,-21.354 64.498,-21.354 ; 63.482,-21.328 64.498,-21.328 ; 63.482,-21.303 64.498,-21.303 ; 63.482,-21.278 64.498,-21.278 ; 63.482,-21.252 64.498,-21.252 ; 63.482,-21.227 64.498,-21.227 ; 63.482,-21.201 64.498,-21.201 ; 63.482,-21.176 64.498,-21.176 ; 63.482,-21.151 64.498,-21.151 ; 63.482,-21.125 64.498,-21.125 ; 63.482,-21.1 64.498,-21.1 ; 63.482,-21.074 64.498,-21.074 ; 63.482,-21.049 64.498,-21.049 ; 63.482,-21.024 64.498,-21.024 ; 63.482,-20.998 64.498,-20.998 ; 63.482,-20.973 64.498,-20.973 ; 63.482,-20.947 64.498,-20.947 ; 63.482,-20.922 64.498,-20.922 ; 63.482,-20.897 64.498,-20.897 ; 63.482,-20.871 64.498,-20.871 ; 63.482,-20.846 64.498,-20.846 ; 63.482,-20.82 64.498,-20.82 ; 63.482,-20.795 64.498,-20.795 ; 63.482,-20.77 64.498,-20.77 ; 63.482,-20.744 64.498,-20.744 ; 63.482,-20.719 64.498,-20.719 ; 63.482,-20.693 64.498,-20.693 ; 63.482,-20.668 64.498,-20.668 ; 63.482,-20.643 64.498,-20.643 ; 63.482,-20.617 64.498,-20.617 ; 63.482,-20.592 64.498,-20.592 ; 63.482,-20.566 64.498,-20.566 ; 63.482,-20.541 64.498,-20.541 ; 63.482,-20.516 64.498,-20.516 ; 63.482,-20.49 64.498,-20.49 ; 63.482,-20.465 64.498,-20.465 ; 63.482,-20.439 64.498,-20.439 ; 63.482,-19.068 63.812,-19.068 ; 63.482,-19.042 63.812,-19.042 ; 63.482,-19.017 63.812,-19.017 ; 63.482,-18.992 63.812,-18.992 ; 63.482,-18.966 63.812,-18.966 ; 63.482,-18.941 63.812,-18.941 ; 63.482,-18.915 63.812,-18.915 ; 63.482,-18.89 63.812,-18.89 ; 63.482,-18.865 63.812,-18.865 ; 63.482,-18.839 63.812,-18.839 ; 63.482,-18.814 63.812,-18.814 ; 63.482,-18.788 63.812,-18.788 ; 63.482,-18.382 63.812,-18.382 ; 63.482,-18.357 63.812,-18.357 ; 63.482,-18.331 63.812,-18.331 ; 63.482,-18.306 63.812,-18.306 ; 63.482,-18.28 63.812,-18.28 ; 63.482,-18.255 63.812,-18.255 ; 63.482,-18.23 63.812,-18.23 ; 63.482,-18.204 63.812,-18.204 ; 63.482,-18.179 63.812,-18.179 ; 63.482,-18.153 63.812,-18.153 ; 63.482,-18.128 65.158,-18.128 ; 63.482,-18.103 65.158,-18.103 ; 63.482,-17.772 65.158,-17.772 ; 63.482,-17.747 65.158,-17.747 ; 63.482,-17.722 65.158,-17.722 ; 63.482,-17.696 65.158,-17.696 ; 63.482,-17.671 65.158,-17.671 ; 63.482,-17.645 65.158,-17.645 ; 63.482,-17.62 65.158,-17.62 ; 63.482,-17.595 65.158,-17.595 ; 63.482,-17.569 65.158,-17.569 ; 63.482,-17.544 65.158,-17.544 ; 63.482,-17.518 65.158,-17.518 ; 63.482,-17.493 65.158,-17.493 ; 63.482,-17.468 65.158,-17.468 ; 63.482,-16.401 64.498,-16.401 ; 63.482,-16.375 64.498,-16.375 ; 63.482,-16.35 64.498,-16.35 ; 63.482,-16.325 64.498,-16.325 ; 63.482,-16.299 64.498,-16.299 ; 63.482,-16.274 64.498,-16.274 ; 63.482,-16.248 64.498,-16.248 ; 63.482,-16.223 64.498,-16.223 ; 63.482,-16.198 64.498,-16.198 ; 63.482,-16.172 64.498,-16.172 ; 63.482,-16.147 64.498,-16.147 ; 63.482,-16.121 64.498,-16.121 ; 63.482,-16.096 63.812,-16.096 ; 63.482,-16.071 63.812,-16.071 ; 63.482,-16.045 63.812,-16.045 ; 63.482,-16.02 63.812,-16.02 ; 63.482,-15.994 63.812,-15.994 ; 63.482,-15.969 63.812,-15.969 ; 63.482,-15.944 63.812,-15.944 ; 63.482,-15.918 63.812,-15.918 ; 63.482,-15.893 63.812,-15.893 ; 63.482,-15.867 63.812,-15.867 ; 63.482,-15.842 63.812,-15.842 ; 63.482,-15.817 63.812,-15.817 ; 63.482,-15.791 63.812,-15.791 ; 63.482,-15.41 64.168,-15.41 ; 63.482,-15.385 64.168,-15.385 ; 63.482,-15.359 64.168,-15.359 ; 63.482,-15.334 64.168,-15.334 ; 63.482,-15.309 64.168,-15.309 ; 63.482,-15.283 64.168,-15.283 ; 63.482,-15.258 64.168,-15.258 ; 63.482,-15.232 64.168,-15.232 ; 63.482,-15.207 64.168,-15.207 ; 63.482,-15.182 64.168,-15.182 ; 63.482,-15.156 64.168,-15.156 ; 63.482,-15.131 64.168,-15.131 ; 63.482,-15.105 64.498,-15.105 ; 63.482,-15.08 64.498,-15.08 ; 63.482,-15.055 64.498,-15.055 ; 63.482,-15.029 64.498,-15.029 ; 63.482,-15.004 64.498,-15.004 ; 63.482,-14.978 64.498,-14.978 ; 63.482,-14.953 64.498,-14.953 ; 63.482,-14.928 64.498,-14.928 ; 63.482,-14.902 64.498,-14.902 ; 63.482,-14.877 64.498,-14.877 ; 63.482,-14.851 64.498,-14.851 ; 63.482,-14.826 64.498,-14.826 ; 63.482,-14.801 64.498,-14.801 ; 63.482,-11.448 64.498,-11.448 ; 63.482,-11.422 64.498,-11.422 ; 63.482,-11.397 64.498,-11.397 ; 63.482,-11.372 64.498,-11.372 ; 63.482,-11.346 64.498,-11.346 ; 63.482,-11.321 64.498,-11.321 ; 63.482,-11.295 64.498,-11.295 ; 63.482,-11.27 64.498,-11.27 ; 63.482,-11.245 64.498,-11.245 ; 63.482,-11.219 64.498,-11.219 ; 63.482,-11.194 64.498,-11.194 ; 63.482,-11.168 64.498,-11.168 ; 63.482,-11.143 64.498,-11.143 ; 63.482,-11.118 64.498,-11.118 ; 63.482,-11.092 64.498,-11.092 ; 63.482,-11.067 64.498,-11.067 ; 63.482,-11.041 64.498,-11.041 ; 63.482,-11.016 64.498,-11.016 ; 63.482,-10.991 64.498,-10.991 ; 63.482,-10.965 64.498,-10.965 ; 63.482,-10.94 64.498,-10.94 ; 63.482,-10.914 64.498,-10.914 ; 63.482,-10.889 64.498,-10.889 ; 63.482,-10.864 64.498,-10.864 ; 63.482,-10.838 64.498,-10.838 ; 63.482,-10.813 64.498,-10.813 ; 63.482,-10.787 64.498,-10.787 ; 63.482,-10.762 64.498,-10.762 ; 63.482,-10.737 64.498,-10.737 ; 63.482,-10.711 64.498,-10.711 ; 63.482,-10.686 64.498,-10.686 ; 63.482,-10.66 64.498,-10.66 ; 63.482,-10.635 64.498,-10.635 ; 63.482,-10.61 64.498,-10.61 ; 63.482,-10.584 64.498,-10.584 ; 63.482,-10.559 64.498,-10.559 ; 63.482,-10.533 64.498,-10.533 ; 63.482,-10.508 64.498,-10.508 ; 63.482,-10.483 64.498,-10.483 ; 63.482,-10.457 64.498,-10.457 ; 63.812,-18.077 64.168,-18.077 ; 63.812,-18.052 64.168,-18.052 ; 63.812,-18.026 64.168,-18.026 ; 63.812,-18.001 64.168,-18.001 ; 63.812,-17.976 64.168,-17.976 ; 63.812,-17.95 64.168,-17.95 ; 63.812,-17.925 64.168,-17.925 ; 63.812,-17.899 64.168,-17.899 ; 63.812,-17.874 64.168,-17.874 ; 63.812,-17.849 64.168,-17.849 ; 63.812,-17.823 64.168,-17.823 ; 63.812,-17.798 64.168,-17.798 ; 63.812,-14.47 64.168,-14.47 ; 63.812,-14.445 64.168,-14.445 ; 63.812,-14.42 64.168,-14.42 ; 63.812,-14.394 64.168,-14.394 ; 63.812,-14.369 64.168,-14.369 ; 63.812,-14.343 64.168,-14.343 ; 63.812,-14.318 64.168,-14.318 ; 63.812,-14.293 64.168,-14.293 ; 63.812,-14.267 64.168,-14.267 ; 63.812,-14.242 64.168,-14.242 ; 63.812,-14.216 64.168,-14.216 ; 63.812,-14.191 64.168,-14.191 ; 63.812,-14.166 64.168,-14.166 ; 63.812,-14.14 64.168,-14.14 ; 63.812,-14.115 65.158,-14.115 ; 63.812,-14.089 65.158,-14.089 ; 63.812,-14.064 65.158,-14.064 ; 63.812,-14.039 65.158,-14.039 ; 63.812,-14.013 65.158,-14.013 ; 63.812,-13.988 65.158,-13.988 ; 63.812,-13.962 65.158,-13.962 ; 63.812,-13.937 65.158,-13.937 ; 63.812,-13.912 65.158,-13.912 ; 63.812,-13.886 65.158,-13.886 ; 63.812,-13.861 65.158,-13.861 ; 63.812,-13.835 65.158,-13.835 ; 63.812,-13.81 65.158,-13.81 ; 63.812,-13.785 65.158,-13.785 ; 63.812,-13.759 65.158,-13.759 ; 63.812,-13.734 65.158,-13.734 ; 63.812,-13.708 65.158,-13.708 ; 63.812,-13.683 65.158,-13.683 ; 63.812,-13.658 65.158,-13.658 ; 63.812,-13.632 65.158,-13.632 ; 63.812,-13.607 65.158,-13.607 ; 63.812,-13.581 65.158,-13.581 ; 63.812,-13.556 65.158,-13.556 ; 63.812,-13.531 65.158,-13.531 ; 63.812,-13.505 65.158,-13.505 ; 63.812,-13.48 65.158,-13.48 ; 63.812,-13.454 65.158,-13.454 ; 63.812,-13.429 64.193,-13.429 ; 63.812,-13.404 64.168,-13.404 ; 63.812,-13.378 64.168,-13.378 ; 63.812,-13.353 64.168,-13.353 ; 63.812,-13.327 64.168,-13.327 ; 63.812,-13.302 64.168,-13.302 ; 63.812,-13.277 64.168,-13.277 ; 63.812,-13.251 64.168,-13.251 ; 63.812,-13.226 64.168,-13.226 ; 63.812,-13.2 64.168,-13.2 ; 63.812,-13.175 64.168,-13.175 ; 63.812,-13.15 64.168,-13.15 ; 63.812,-13.124 64.168,-13.124 ; 63.812,-13.099 64.168,-13.099 ; 63.812,-13.073 64.168,-13.073 ; 63.812,-13.048 64.168,-13.048 ; 63.812,-13.023 64.168,-13.023 ; 63.812,-12.997 64.168,-12.997 ; 63.812,-12.972 64.168,-12.972 ; 63.812,-12.946 64.168,-12.946 ; 63.812,-12.921 64.168,-12.921 ; 63.812,-12.896 64.168,-12.896 ; 63.812,-12.87 64.168,-12.87 ; 63.812,-12.845 64.168,-12.845 ; 63.812,-12.819 64.168,-12.819 ; 64.117,-19.068 64.853,-19.068 ; 64.117,-19.042 64.853,-19.042 ; 64.117,-19.017 64.853,-19.017 ; 64.117,-18.992 64.853,-18.992 ; 64.117,-18.966 64.853,-18.966 ; 64.117,-18.941 64.853,-18.941 ; 64.117,-18.915 64.853,-18.915 ; 64.117,-18.89 64.853,-18.89 ; 64.117,-18.865 64.853,-18.865 ; 64.117,-18.839 64.853,-18.839 ; 64.117,-18.814 64.853,-18.814 ; 64.117,-18.788 64.853,-18.788 ; 64.117,-18.382 64.853,-18.382 ; 64.117,-18.357 64.853,-18.357 ; 64.117,-18.331 64.853,-18.331 ; 64.117,-18.306 64.853,-18.306 ; 64.117,-18.28 64.853,-18.28 ; 64.117,-18.255 64.853,-18.255 ; 64.117,-18.23 64.853,-18.23 ; 64.117,-18.204 64.853,-18.204 ; 64.117,-18.179 64.853,-18.179 ; 64.117,-18.153 64.853,-18.153 ; 64.117,-16.096 64.498,-16.096 ; 64.117,-16.071 64.498,-16.071 ; 64.117,-16.045 64.498,-16.045 ; 64.117,-16.02 64.498,-16.02 ; 64.117,-15.994 64.498,-15.994 ; 64.117,-15.969 64.498,-15.969 ; 64.117,-15.944 64.498,-15.944 ; 64.117,-15.918 64.498,-15.918 ; 64.117,-15.893 64.498,-15.893 ; 64.117,-15.867 64.498,-15.867 ; 64.117,-15.842 64.498,-15.842 ; 64.117,-15.817 64.498,-15.817 ; 64.117,-15.791 64.498,-15.791 ; 64.117,-15.766 64.853,-15.766 ; 64.117,-15.74 64.853,-15.74 ; 64.117,-15.715 64.853,-15.715 ; 64.117,-15.69 64.853,-15.69 ; 64.117,-15.664 64.853,-15.664 ; 64.117,-15.639 64.853,-15.639 ; 64.117,-15.613 64.853,-15.613 ; 64.117,-15.588 64.853,-15.588 ; 64.117,-15.563 64.853,-15.563 ; 64.117,-15.537 64.853,-15.537 ; 64.117,-15.512 64.853,-15.512 ; 64.117,-15.486 64.853,-15.486 ; 64.117,-12.743 64.498,-12.743 ; 64.117,-12.718 64.498,-12.718 ; 64.117,-12.692 64.498,-12.692 ; 64.117,-12.667 64.498,-12.667 ; 64.117,-12.642 64.498,-12.642 ; 64.117,-12.616 64.498,-12.616 ; 64.117,-12.591 64.498,-12.591 ; 64.117,-12.565 64.498,-12.565 ; 64.117,-12.54 64.498,-12.54 ; 64.117,-12.515 64.498,-12.515 ; 64.117,-12.489 64.498,-12.489 ; 64.117,-12.464 64.498,-12.464 ; 64.168,-12.438 64.472,-12.438 ; 64.472,-17.087 65.158,-17.087 ; 64.472,-17.061 65.158,-17.061 ; 64.472,-17.036 65.158,-17.036 ; 64.472,-17.01 65.158,-17.01 ; 64.472,-16.985 65.158,-16.985 ; 64.472,-16.96 65.158,-16.96 ; 64.472,-16.934 65.158,-16.934 ; 64.472,-16.909 65.158,-16.909 ; 64.472,-16.883 65.158,-16.883 ; 64.472,-16.858 65.158,-16.858 ; 64.472,-16.833 65.158,-16.833 ; 64.472,-16.807 65.158,-16.807 ; 64.472,-14.47 65.158,-14.47 ; 64.472,-14.445 65.158,-14.445 ; 64.472,-14.42 65.158,-14.42 ; 64.472,-14.394 65.158,-14.394 ; 64.472,-14.369 65.158,-14.369 ; 64.472,-14.343 65.158,-14.343 ; 64.472,-14.318 65.158,-14.318 ; 64.472,-14.293 65.158,-14.293 ; 64.472,-14.267 65.158,-14.267 ; 64.472,-14.242 65.158,-14.242 ; 64.472,-14.216 65.158,-14.216 ; 64.472,-14.191 65.158,-14.191 ; 64.472,-14.166 65.158,-14.166 ; 64.472,-14.14 65.158,-14.14 ; 64.472,-13.124 65.158,-13.124 ; 64.472,-13.099 64.853,-13.099 ; 64.472,-13.073 64.853,-13.073 ; 64.472,-13.048 64.853,-13.048 ; 64.472,-13.023 64.853,-13.023 ; 64.472,-12.997 64.853,-12.997 ; 64.472,-12.972 64.853,-12.972 ; 64.472,-12.946 64.853,-12.946 ; 64.472,-12.921 64.853,-12.921 ; 64.472,-12.896 64.853,-12.896 ; 64.472,-12.87 64.853,-12.87 ; 64.472,-12.845 64.853,-12.845 ; 64.472,-12.819 64.853,-12.819 ; 64.777,-21.735 65.158,-21.735 ; 64.777,-17.137 65.158,-17.137 ; 64.777,-17.112 65.158,-17.112 ; 64.777,-13.429 65.158,-13.429 ; 64.777,-10.152 65.158,-10.152 ; 64.803,-21.709 65.158,-21.709 ; 64.803,-21.684 65.158,-21.684 ; 64.803,-21.659 65.158,-21.659 ; 64.803,-21.633 65.158,-21.633 ; 64.803,-21.608 65.158,-21.608 ; 64.803,-21.582 65.158,-21.582 ; 64.803,-21.557 65.158,-21.557 ; 64.803,-21.532 65.158,-21.532 ; 64.803,-21.506 65.158,-21.506 ; 64.803,-21.481 65.158,-21.481 ; 64.803,-21.455 65.158,-21.455 ; 64.803,-21.43 65.158,-21.43 ; 64.803,-21.405 65.158,-21.405 ; 64.803,-21.379 65.158,-21.379 ; 64.803,-21.354 65.158,-21.354 ; 64.803,-21.328 65.158,-21.328 ; 64.803,-21.303 65.158,-21.303 ; 64.803,-21.278 65.158,-21.278 ; 64.803,-21.252 65.158,-21.252 ; 64.803,-21.227 65.158,-21.227 ; 64.803,-21.201 65.158,-21.201 ; 64.803,-21.176 65.158,-21.176 ; 64.803,-21.151 65.158,-21.151 ; 64.803,-21.125 65.158,-21.125 ; 64.803,-21.1 65.158,-21.1 ; 64.803,-21.074 65.158,-21.074 ; 64.803,-21.049 65.158,-21.049 ; 64.803,-21.024 65.158,-21.024 ; 64.803,-20.998 65.158,-20.998 ; 64.803,-20.973 65.158,-20.973 ; 64.803,-20.947 65.158,-20.947 ; 64.803,-20.922 65.158,-20.922 ; 64.803,-20.897 65.158,-20.897 ; 64.803,-20.871 65.158,-20.871 ; 64.803,-20.846 65.158,-20.846 ; 64.803,-20.82 65.158,-20.82 ; 64.803,-20.795 65.158,-20.795 ; 64.803,-20.77 65.158,-20.77 ; 64.803,-20.744 65.158,-20.744 ; 64.803,-20.719 65.158,-20.719 ; 64.803,-20.693 65.158,-20.693 ; 64.803,-20.668 65.158,-20.668 ; 64.803,-20.643 65.158,-20.643 ; 64.803,-20.617 65.158,-20.617 ; 64.803,-20.592 65.158,-20.592 ; 64.803,-20.566 65.158,-20.566 ; 64.803,-20.541 65.158,-20.541 ; 64.803,-20.516 65.158,-20.516 ; 64.803,-20.49 65.158,-20.49 ; 64.803,-20.465 65.158,-20.465 ; 64.803,-20.439 65.158,-20.439 ; 64.803,-20.414 65.158,-20.414 ; 64.803,-20.389 65.158,-20.389 ; 64.803,-20.363 65.158,-20.363 ; 64.803,-20.338 65.158,-20.338 ; 64.803,-20.312 65.158,-20.312 ; 64.803,-20.287 65.158,-20.287 ; 64.803,-20.262 65.158,-20.262 ; 64.803,-20.236 65.158,-20.236 ; 64.803,-20.211 65.158,-20.211 ; 64.803,-20.185 65.158,-20.185 ; 64.803,-20.16 65.158,-20.16 ; 64.803,-20.135 65.158,-20.135 ; 64.803,-19.449 65.158,-19.449 ; 64.803,-19.423 65.158,-19.423 ; 64.803,-19.398 65.158,-19.398 ; 64.803,-19.373 65.158,-19.373 ; 64.803,-19.347 65.158,-19.347 ; 64.803,-19.322 65.158,-19.322 ; 64.803,-19.296 65.158,-19.296 ; 64.803,-19.271 65.158,-19.271 ; 64.803,-19.246 65.158,-19.246 ; 64.803,-19.22 65.158,-19.22 ; 64.803,-19.195 65.158,-19.195 ; 64.803,-19.169 65.158,-19.169 ; 64.803,-19.144 65.158,-19.144 ; 64.803,-18.738 65.158,-18.738 ; 64.803,-18.712 65.158,-18.712 ; 64.803,-18.687 65.158,-18.687 ; 64.803,-18.661 65.158,-18.661 ; 64.803,-18.636 65.158,-18.636 ; 64.803,-18.611 65.158,-18.611 ; 64.803,-18.585 65.158,-18.585 ; 64.803,-18.56 65.158,-18.56 ; 64.803,-18.534 65.158,-18.534 ; 64.803,-18.509 65.158,-18.509 ; 64.803,-18.484 65.158,-18.484 ; 64.803,-18.458 65.158,-18.458 ; 64.803,-18.077 65.158,-18.077 ; 64.803,-18.052 65.158,-18.052 ; 64.803,-18.026 65.158,-18.026 ; 64.803,-18.001 65.158,-18.001 ; 64.803,-17.976 65.158,-17.976 ; 64.803,-17.95 65.158,-17.95 ; 64.803,-17.925 65.158,-17.925 ; 64.803,-17.899 65.158,-17.899 ; 64.803,-17.874 65.158,-17.874 ; 64.803,-17.849 65.158,-17.849 ; 64.803,-17.823 65.158,-17.823 ; 64.803,-17.798 65.158,-17.798 ; 64.803,-17.391 65.158,-17.391 ; 64.803,-17.366 65.158,-17.366 ; 64.803,-17.341 65.158,-17.341 ; 64.803,-17.315 65.158,-17.315 ; 64.803,-17.29 65.158,-17.29 ; 64.803,-17.264 65.158,-17.264 ; 64.803,-17.239 65.158,-17.239 ; 64.803,-17.214 65.158,-17.214 ; 64.803,-17.188 65.158,-17.188 ; 64.803,-17.163 65.158,-17.163 ; 64.803,-16.756 65.158,-16.756 ; 64.803,-16.731 65.158,-16.731 ; 64.803,-16.706 65.158,-16.706 ; 64.803,-16.68 65.158,-16.68 ; 64.803,-16.655 65.158,-16.655 ; 64.803,-16.629 65.158,-16.629 ; 64.803,-16.604 65.158,-16.604 ; 64.803,-16.579 65.158,-16.579 ; 64.803,-16.553 65.158,-16.553 ; 64.803,-16.528 65.158,-16.528 ; 64.803,-16.502 65.158,-16.502 ; 64.803,-16.477 65.158,-16.477 ; 64.803,-16.452 65.158,-16.452 ; 64.803,-16.426 65.158,-16.426 ; 64.803,-16.401 65.158,-16.401 ; 64.803,-16.375 65.158,-16.375 ; 64.803,-16.35 65.158,-16.35 ; 64.803,-16.325 65.158,-16.325 ; 64.803,-16.299 65.158,-16.299 ; 64.803,-16.274 65.158,-16.274 ; 64.803,-16.248 65.158,-16.248 ; 64.803,-16.223 65.158,-16.223 ; 64.803,-16.198 65.158,-16.198 ; 64.803,-16.172 65.158,-16.172 ; 64.803,-16.147 65.158,-16.147 ; 64.803,-16.121 65.158,-16.121 ; 64.803,-15.105 65.158,-15.105 ; 64.803,-15.08 65.158,-15.08 ; 64.803,-15.055 65.158,-15.055 ; 64.803,-15.029 65.158,-15.029 ; 64.803,-15.004 65.158,-15.004 ; 64.803,-14.978 65.158,-14.978 ; 64.803,-14.953 65.158,-14.953 ; 64.803,-14.928 65.158,-14.928 ; 64.803,-14.902 65.158,-14.902 ; 64.803,-14.877 65.158,-14.877 ; 64.803,-14.851 65.158,-14.851 ; 64.803,-14.826 65.158,-14.826 ; 64.803,-14.801 65.158,-14.801 ; 64.803,-14.775 65.158,-14.775 ; 64.803,-14.75 65.158,-14.75 ; 64.803,-14.724 65.158,-14.724 ; 64.803,-14.699 65.158,-14.699 ; 64.803,-14.674 65.158,-14.674 ; 64.803,-14.648 65.158,-14.648 ; 64.803,-14.623 65.158,-14.623 ; 64.803,-14.597 65.158,-14.597 ; 64.803,-14.572 65.158,-14.572 ; 64.803,-14.547 65.158,-14.547 ; 64.803,-14.521 65.158,-14.521 ; 64.803,-14.496 65.158,-14.496 ; 64.803,-13.404 65.158,-13.404 ; 64.803,-13.378 65.158,-13.378 ; 64.803,-13.353 65.158,-13.353 ; 64.803,-13.327 65.158,-13.327 ; 64.803,-13.302 65.158,-13.302 ; 64.803,-13.277 65.158,-13.277 ; 64.803,-13.251 65.158,-13.251 ; 64.803,-13.226 65.158,-13.226 ; 64.803,-13.2 65.158,-13.2 ; 64.803,-13.175 65.158,-13.175 ; 64.803,-13.15 65.158,-13.15 ; 64.803,-11.753 65.158,-11.753 ; 64.803,-11.727 65.158,-11.727 ; 64.803,-11.702 65.158,-11.702 ; 64.803,-11.676 65.158,-11.676 ; 64.803,-11.651 65.158,-11.651 ; 64.803,-11.626 65.158,-11.626 ; 64.803,-11.6 65.158,-11.6 ; 64.803,-11.575 65.158,-11.575 ; 64.803,-11.549 65.158,-11.549 ; 64.803,-11.524 65.158,-11.524 ; 64.803,-11.499 65.158,-11.499 ; 64.803,-11.473 65.158,-11.473 ; 64.803,-11.448 65.158,-11.448 ; 64.803,-11.422 65.158,-11.422 ; 64.803,-11.397 65.158,-11.397 ; 64.803,-11.372 65.158,-11.372 ; 64.803,-11.346 65.158,-11.346 ; 64.803,-11.321 65.158,-11.321 ; 64.803,-11.295 65.158,-11.295 ; 64.803,-11.27 65.158,-11.27 ; 64.803,-11.245 65.158,-11.245 ; 64.803,-11.219 65.158,-11.219 ; 64.803,-11.194 65.158,-11.194 ; 64.803,-11.168 65.158,-11.168 ; 64.803,-11.143 65.158,-11.143 ; 64.803,-11.118 65.158,-11.118 ; 64.803,-11.092 65.158,-11.092 ; 64.803,-11.067 65.158,-11.067 ; 64.803,-11.041 65.158,-11.041 ; 64.803,-11.016 65.158,-11.016 ; 64.803,-10.991 65.158,-10.991 ; 64.803,-10.965 65.158,-10.965 ; 64.803,-10.94 65.158,-10.94 ; 64.803,-10.914 65.158,-10.914 ; 64.803,-10.889 65.158,-10.889 ; 64.803,-10.864 65.158,-10.864 ; 64.803,-10.838 65.158,-10.838 ; 64.803,-10.813 65.158,-10.813 ; 64.803,-10.787 65.158,-10.787 ; 64.803,-10.762 65.158,-10.762 ; 64.803,-10.737 65.158,-10.737 ; 64.803,-10.711 65.158,-10.711 ; 64.803,-10.686 65.158,-10.686 ; 64.803,-10.66 65.158,-10.66 ; 64.803,-10.635 65.158,-10.635 ; 64.803,-10.61 65.158,-10.61 ; 64.803,-10.584 65.158,-10.584 ; 64.803,-10.559 65.158,-10.559 ; 64.803,-10.533 65.158,-10.533 ; 64.803,-10.508 65.158,-10.508 ; 64.803,-10.483 65.158,-10.483 ; 64.803,-10.457 65.158,-10.457 ; 64.803,-10.432 65.158,-10.432 ; 64.803,-10.406 65.158,-10.406 ; 64.803,-10.381 65.158,-10.381 ; 64.803,-10.356 65.158,-10.356 ; 64.803,-10.33 65.158,-10.33 ; 64.803,-10.305 65.158,-10.305 ; 64.803,-10.279 65.158,-10.279 ; 64.803,-10.254 65.158,-10.254 ; 64.803,-10.229 65.158,-10.229 ; 64.803,-10.203 65.158,-10.203 ; 64.803,-10.178 65.158,-10.178

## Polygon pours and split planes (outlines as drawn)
GND on Top Layer "Top Layer-GND" (solid, pour order 8): 43.5,3.5
GND on Top Layer "Bottom Layer-No Net" (solid, remove dead copper, pour order 32): 40.132,-7.45 40.142,-7.46 78.15,-7.46 78.15,-43 40.091,-43 40.05,-42.959
GND on Bottom Layer "Bottom Layer-No Net" (solid, remove dead copper, pour order 34): 40.1,-7.574 40.124,-7.55 78.15,-7.55 78.15,-42.873 78.1,-42.923 40.209,-42.923 40.132,-43

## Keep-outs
Keep-Out Layer:
  lines w0.2: 40.132,-42.65 ccw(c40.455,-42.65) 40.455,-42.973 ; 40.132,-42.6 40.132,-0.223 ; 40.133,-0.223 cw(c40.456,-0.223) 40.456,0.1 77.841,0.1 ; 40.455,-42.959 77.773,-42.959 77.809,-42.923 ccw(c77.809,-42.6) 78.132,-42.6 78.132,-0.183 ccw(c77.841,-0.183) 77.841,0.108

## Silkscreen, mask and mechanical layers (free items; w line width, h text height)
Bottom Solder:
  drawing of 4510 lines, arcs and shapes, not listed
